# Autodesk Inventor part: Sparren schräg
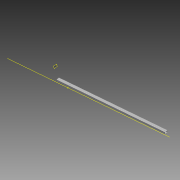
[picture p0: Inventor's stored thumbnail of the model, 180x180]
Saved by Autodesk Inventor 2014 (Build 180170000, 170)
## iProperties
Created: 2013-09
Part Number: Sparren schräg
Material: Stahl
Document SubType Name: Modeling
Designer: Stefan Tammegger
Density: 7.85 g/cm^3
Appearance: Stahl
Mass: 32749.1 g
Surface Area: 20883.4 cm^2
Volume: 4171.86 cm^3
Author: Stefan Tammegger
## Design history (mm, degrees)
node "Blöcke"
  sketch "FR 100_60_4"
    geometry: L1 (25.014, 27.2)-(-66.986, 27.2); L2 (-70.986, 31.2)-(-70.986, 83.2); L3 (-66.986, 87.2)-(25.014, 87.2); L4 (29.014, 83.2)-(29.014, 31.2); L5 (25.014, 31.2)-(-66.986, 31.2); L6 (-66.986, 31.2)-(-66.986, 83.2); L7 (-66.986, 83.2)-(25.014, 83.2); L8 (25.014, 83.2)-(25.014, 31.2); A1 r 4 centre (25.014, 31.2) between (25.014, 27.2) and (29.014, 31.2); A2 r 4 centre (25.014, 83.2) between (29.014, 83.2) and (25.014, 87.2); A3 r 4 centre (-66.986, 83.2) between (-66.986, 87.2) and (-70.986, 83.2); A4 r 4 centre (-66.986, 31.2) between (-70.986, 31.2) and (-66.986, 27.2); 4 further points
    constraints: 16 end point, 8 point on circle, 8 tangent, 6 point on line, 4 centre point, 4 parallel, 3 equal radius, 2 perpendicular, 1 horizontal, 1 midpoint, 3 other
    dimensions: "d0" = 100 distance of point (-70.986, 87.2) point (29.014, 87.2); "d1" = 60 distance of point (-70.986, 27.2) point (-70.986, 87.2); "d2" = 4 distance between parallel lines of L4 L8; "d3" = 4 radius of A1
workaxis "Arbeitsachse1"
workpoint "Arbeitspunkt1"
workplane "Arbeitsebene2"
  workpoint "Arbeitspunkt3"
sketch "Skizze1"
  geometry: L1 (77.991, 3698.069)-(0, 0) reference; L2 (11.056, -4.98)-(-168.299, -4.955) reference; L3 (-182.049, -0.225)-(-2.695, -0.25) reference; 1 further point
  dimensions: "d4" = 3 dimension on L1.end; "d5" = 20 dimension on L1.end
extrude "Extrusion1" new body sketch "Skizze1" distance "d6" = 3070; taper "d8" = 0 deg; dims "d7" = 400, "d9" = 0
workplane "Arbeitsebene3"
feature "Trennen1"
sketch "Skizze2"
  geometry: 2 further points; 1 other entity
  constraints: 1 other
hole "Bohrung1" sketch "Skizze2" at (-3041.364, 45.777) diameter "d11" = 14; stored, may be unused: countersink angle "d15" = 90 deg, drill point angle "d17" = 118 deg; dims "d12" = 6, "d13" = 4, "d14" = 2, "d16" = 8
sketch "Skizze3"
  geometry: 2 further points; 1 other entity
  constraints: 1 other
hole "Bohrung2" sketch "Skizze3" at (-44.1, 45.865) diameter "d18" = 14; stored, may be unused: countersink angle "d22" = 90 deg, drill point angle "d24" = 118 deg; dims "d19" = 6, "d20" = 4, "d21" = 2, "d23" = 8
sketch "Skizze4"
  geometry: C1 r 4.75 at (89.16, 26) reference; C2 r 4.703 at (559.16, 26) reference; C3 r 4.703 at (1029.16, 26) reference; C4 r 4.75 at (1499.16, 26) reference; C5 r 4.703 at (1969.16, 26) reference; C6 r 4.703 at (2439.16, 26) reference; C7 r 4.75 at (2909.16, 26) reference; C8 r 4.75 at (3379.16, 26) reference; 1 further point
hole "Bohrung3" sketch "Skizze4" at (89.16, 26), (559.16, 26), (1029.16, 26), (1499.16, 26), (1969.16, 26), (2439.16, 26), (2909.16, 26), (3379.16, 26) diameter "d25" = 4.134; stored, may be unused: countersink angle "d29" = 90 deg, drill point angle "d31" = 118 deg; dims "d26" = 6, "d27" = 4, "d28" = 2, "d30" = 8
node "Volumenkörper1"
node "Referenz1"
node "Referenz2"
node "Referenz3"
node "Referenz4"
node "Referenz5"
node "Referenz6"
node "Referenz7"
node "Referenz8"
node "Referenz9"
node "Referenz10"
node "Referenz11"
node "Referenz12"
node "Referenz13"
node "FR 100_60_4:1" dims "d4" = 3, "d5" = 20
